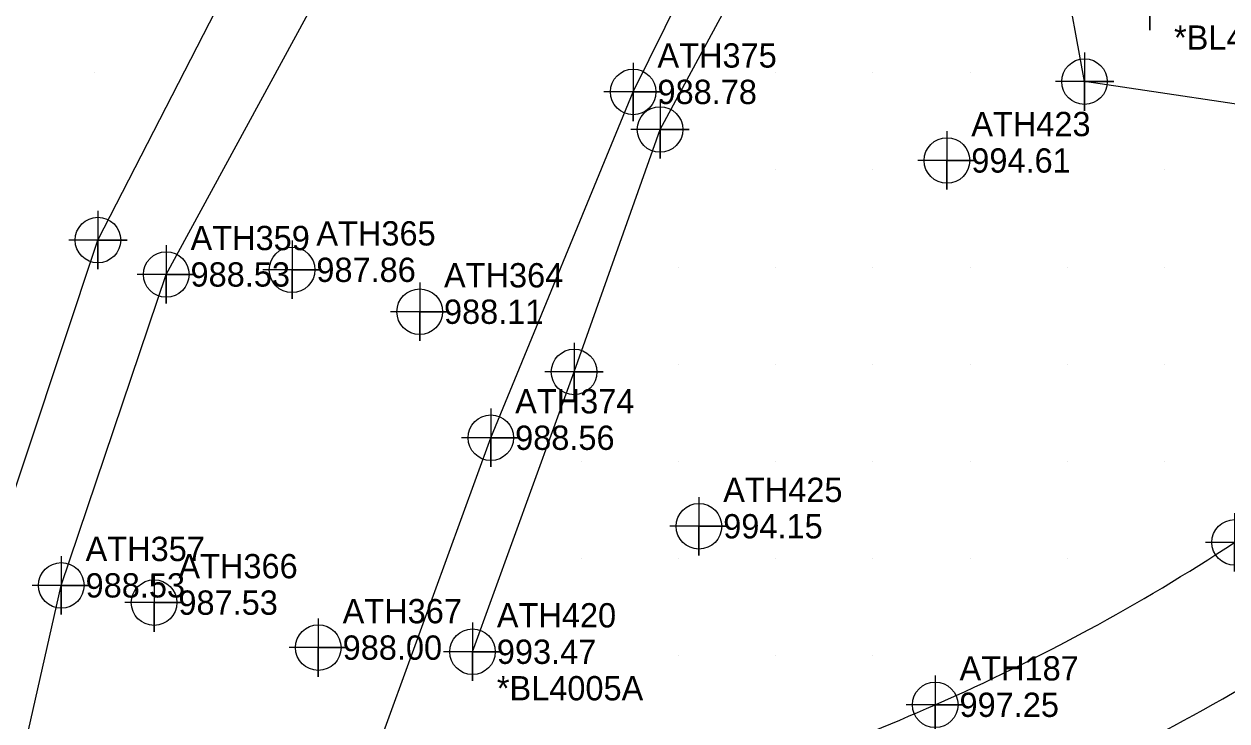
# Model space of a CAD drawing. Extents: x 1116680 to 1117499, y 661040 to 661703.
# Drawn here: x 1117062.7 to 1117186.4, y 661403.3 to 661475 of the extents above; entities that cross this region are included whole.
import ezdxf

# ---------------------------------------------------------------- set-up
doc = ezdxf.new("R2010")
doc.units = 0
for name, color, linetype in [('Exist DTM Breakline', 7, 'Continuous'), ('Exist DTM Breakline Cogo Comment', 7, 'Continuous'), ('Exist DTM Breakline Cogo Elevation', 7, 'Continuous'), ('Exist DTM Breakline Cogo Number', 7, 'Continuous'), ('Exist DTM Breakline Cogo Point CELL', 7, 'Continuous'), ('Exist DTM Crownline', 7, 'Continuous'), ('Exist DTM Drainline Cogo Elevation', 7, 'Continuous'), ('Exist DTM Drainline Cogo Number', 7, 'Continuous'), ('Exist DTM Drainline Cogo Point CELL', 7, 'Continuous'), ('Exist DTM QL2 LIDAR Elevation Point', 7, 'Continuous'), ('Exist DTM Regular Point CELL', 7, 'Continuous'), ('Exist DTM Regular Point Cogo Elevation', 7, 'Continuous'), ('Exist DTM Regular Point Cogo Number', 7, 'Continuous'), ('Exist DTM Regular Point Underwater CELL', 7, 'Continuous'), ('Exist DTM Regular Point Underwater Cogo Elevation', 7, 'Continuous'), ('Exist DTM Regular Point Underwater Cogo Number', 7, 'Continuous'), ('Exist Hydro Stream or Body of Water', 7, 'Continuous'), ('Exist Roads EOP', 7, 'Continuous'), ('Exist Roads EOP Cogo Elevation', 7, 'Continuous'), ('Exist Roads EOP Cogo Number', 7, 'Continuous'), ('Exist Roads EOP Cogo Point CELL', 7, 'Continuous')]:
    doc.layers.add(name, color=color, linetype=linetype)

msp = doc.modelspace()

# ---------------------------------------------------------------- linework, layer by layer
at = {"layer": 'Exist DTM Breakline'}
for points in [[(1117128.128, 661464.169), (1117144.878, 661495.181), (1117168.704, 661527.446), (1117200.502, 661571.22), (1117217.144, 661612.812), (1117257.559, 661667.144), (1117273.855, 661694.87)], [(1117194.27, 661465.73), (1117171.77, 661469.09), (1117169.6, 661480.945), (1117189.888, 661502.41), (1117205.863, 661515.329), (1117217.572, 661523.34), (1117225.692, 661514.312), (1117221.27, 661493.665), (1117211.404, 661481.256)], [(1117038.555, 661379.021), (1117059.605, 661420.588), (1117070.329, 661452.789), (1117088.813, 661488.846)], [(1117108.846, 661410.435), (1117119.29, 661439.222), (1117128.128, 661464.169)]]:
    msp.add_lwpolyline(points, dxfattribs=at)
at = {"layer": 'Exist DTM Breakline Cogo Point CELL'}
for points in [[(1117178.472, 661480.376), (1117178.472, 661474.376), (1117178.472, 661477.376), (1117181.472, 661477.376), (1117175.472, 661477.376)], [(1117171.77, 661472.09), (1117171.77, 661466.09), (1117171.77, 661469.09), (1117174.77, 661469.09), (1117168.77, 661469.09)], [(1117128.128, 661467.169), (1117128.128, 661461.169), (1117128.128, 661464.169), (1117131.128, 661464.169), (1117125.128, 661464.169)], [(1117070.329, 661455.789), (1117070.329, 661449.789), (1117070.329, 661452.789), (1117073.329, 661452.789), (1117067.329, 661452.789)], [(1117119.29, 661442.222), (1117119.29, 661436.222), (1117119.29, 661439.222), (1117122.29, 661439.222), (1117116.29, 661439.222)], [(1117108.846, 661413.435), (1117108.846, 661407.435), (1117108.846, 661410.435), (1117111.846, 661410.435), (1117105.846, 661410.435)], [(1117108.846, 661413.435), (1117108.846, 661407.435), (1117108.846, 661410.435), (1117111.846, 661410.435), (1117105.846, 661410.435)]]:
    msp.add_lwpolyline(points, dxfattribs=at)
for centre in [(1117171.77, 661469.09), (1117128.128, 661464.169), (1117070.329, 661452.789), (1117119.29, 661439.222), (1117108.846, 661410.435), (1117108.846, 661410.435)]:
    msp.add_circle(centre, 2.344, dxfattribs=at)
at = {"layer": 'Exist DTM Crownline'}
msp.add_spline([(1117128.608, 661382.881), (1117161.083, 661393.544), (1117193.928, 661410.345), (1117229.679, 661438.384), (1117257.918, 661472.931), (1117285.234, 661525.056), (1117305.735, 661573.245), (1117329.129, 661633.315)], degree=3, dxfattribs=at)
at = {"layer": 'Exist DTM Drainline Cogo Point CELL'}
for points in [[(1117125.362, 661471.034), (1117125.362, 661465.034), (1117125.362, 661468.034), (1117128.362, 661468.034), (1117122.362, 661468.034)], [(1117077.352, 661452.252), (1117077.352, 661446.252), (1117077.352, 661449.252), (1117080.352, 661449.252), (1117074.352, 661449.252)], [(1117110.725, 661435.453), (1117110.725, 661429.453), (1117110.725, 661432.453), (1117113.725, 661432.453), (1117107.725, 661432.453)], [(1117066.561, 661420.266), (1117066.561, 661414.266), (1117066.561, 661417.266), (1117069.561, 661417.266), (1117063.561, 661417.266)]]:
    msp.add_lwpolyline(points, dxfattribs=at)
for centre in [(1117125.362, 661468.034), (1117077.352, 661449.252), (1117110.725, 661432.453), (1117066.561, 661417.266)]:
    msp.add_circle(centre, 2.344, dxfattribs=at)
at = {"layer": 'Exist DTM QL2 LIDAR Elevation Point'}
for p, q in [((1117070, 661470), (1117070, 661470)), ((1117140, 661470), (1117140, 661470)), ((1117150, 661470), (1117150, 661470)), ((1117160, 661470), (1117160, 661470)), ((1117140, 661460), (1117140, 661460)), ((1117150, 661460), (1117150, 661460)), ((1117160, 661460), (1117160, 661460)), ((1117170, 661460), (1117170, 661460)), ((1117180, 661460), (1117180, 661460)), ((1117130, 661450), (1117130, 661450)), ((1117140, 661450), (1117140, 661450)), ((1117150, 661450), (1117150, 661450)), ((1117160, 661450), (1117160, 661450)), ((1117170, 661450), (1117170, 661450)), ((1117180, 661450), (1117180, 661450)), ((1117130, 661440), (1117130, 661440)), ((1117140, 661440), (1117140, 661440)), ((1117150, 661440), (1117150, 661440)), ((1117160, 661440), (1117160, 661440)), ((1117170, 661440), (1117170, 661440)), ((1117180, 661440), (1117180, 661440)), ((1117120, 661430), (1117120, 661430)), ((1117130, 661430), (1117130, 661430)), ((1117140, 661430), (1117140, 661430)), ((1117150, 661430), (1117150, 661430)), ((1117160, 661430), (1117160, 661430)), ((1117170, 661430), (1117170, 661430)), ((1117180, 661430), (1117180, 661430)), ((1117120, 661420), (1117120, 661420)), ((1117130, 661420), (1117130, 661420)), ((1117140, 661420), (1117140, 661420)), ((1117150, 661420), (1117150, 661420)), ((1117160, 661420), (1117160, 661420)), ((1117170, 661420), (1117170, 661420)), ((1117120, 661410), (1117120, 661410)), ((1117130, 661410), (1117130, 661410)), ((1117140, 661410), (1117140, 661410)), ((1117150, 661410), (1117150, 661410))]:
    msp.add_line(p, q, dxfattribs=at)
at = {"layer": 'Exist DTM Regular Point CELL'}
for points in [[(1117157.629, 661463.98), (1117157.629, 661457.98), (1117157.629, 661460.98), (1117160.629, 661460.98), (1117154.629, 661460.98)], [(1117132.124, 661426.346), (1117132.124, 661420.346), (1117132.124, 661423.346), (1117135.124, 661423.346), (1117129.124, 661423.346)]]:
    msp.add_lwpolyline(points, dxfattribs=at)
for centre in [(1117157.629, 661460.98), (1117132.124, 661423.346)]:
    msp.add_circle(centre, 2.344, dxfattribs=at)
at = {"layer": 'Exist DTM Regular Point Underwater CELL'}
for points in [[(1117090.29, 661452.73), (1117090.29, 661446.73), (1117090.29, 661449.73), (1117093.29, 661449.73), (1117087.29, 661449.73)], [(1117103.411, 661448.418), (1117103.411, 661442.418), (1117103.411, 661445.418), (1117106.411, 661445.418), (1117100.411, 661445.418)], [(1117076.104, 661418.491), (1117076.104, 661412.491), (1117076.104, 661415.491), (1117079.104, 661415.491), (1117073.104, 661415.491)], [(1117092.991, 661413.862), (1117092.991, 661407.862), (1117092.991, 661410.862), (1117095.991, 661410.862), (1117089.991, 661410.862)]]:
    msp.add_lwpolyline(points, dxfattribs=at)
for centre in [(1117090.29, 661449.73), (1117103.411, 661445.418), (1117076.104, 661415.491), (1117092.991, 661410.862)]:
    msp.add_circle(centre, 2.344, dxfattribs=at)
at = {"layer": 'Exist Hydro Stream or Body of Water'}
for points in [[(1117125.362, 661468.034), (1117140.152, 661498.019), (1117164.523, 661530.702), (1117196.253, 661574.433), (1117208.146, 661610.151), (1117250.567, 661671.867), (1117271.101, 661697.995)], [(1116885.259, 661065.084), (1116909.522, 661128.826), (1116941.429, 661187.261), (1116973.299, 661231.015), (1117008.806, 661288.675), (1117028.625, 661329.39), (1117037.259, 661346.044), (1117054.084, 661350.959), (1117065.864, 661380.085), (1117058.435, 661381.413), (1117066.561, 661417.266), (1117077.352, 661449.252), (1117098.924, 661488.98)], [(1116999.252, 661212.663), (1117035.553, 661269.03), (1117067.842, 661309.057), (1117080.473, 661351.773), (1117079.751, 661359.687), (1117095.986, 661391.983), (1117110.725, 661432.453), (1117125.362, 661468.034)]]:
    msp.add_lwpolyline(points, dxfattribs=at)
at = {"layer": 'Exist Roads EOP'}
for points in [[(1117102.286, 661387.333), (1117126.621, 661394.057), (1117156.418, 661404.979), (1117187.204, 661421.689), (1117219.891, 661448.41), (1117247.012, 661480.823), (1117275.546, 661531.18), (1117296.661, 661577.27), (1117320.803, 661635.676)], [(1117131.334, 661372.856), (1117166.321, 661382.847), (1117200.815, 661399.841), (1117238.067, 661430.322), (1117267.048, 661465.689), (1117295.472, 661519.132), (1117314.821, 661568.418)]]:
    msp.add_spline(points, degree=3, dxfattribs=at)
at = {"layer": 'Exist Roads EOP Cogo Point CELL'}
for points in [[(1117187.204, 661424.689), (1117187.204, 661418.689), (1117187.204, 661421.689), (1117190.204, 661421.689), (1117184.204, 661421.689)], [(1117156.418, 661407.979), (1117156.418, 661401.979), (1117156.418, 661404.979), (1117159.418, 661404.979), (1117153.418, 661404.979)]]:
    msp.add_lwpolyline(points, dxfattribs=at)
for centre in [(1117187.204, 661421.689), (1117156.418, 661404.979)]:
    msp.add_circle(centre, 2.344, dxfattribs=at)

# ---------------------------------------------------------------- texts
at = {"layer": 'Exist DTM Breakline Cogo Comment'}
for s, p in [('*BL4005D', (1117180.972, 661472.376)), ('*BL4005A', (1117111.346, 661405.435)), ('*BL4005A', (1117111.346, 661405.435))]:
    msp.add_text(s, height=2.5, dxfattribs=at).set_placement(p)
at = {"layer": 'Exist DTM Breakline Cogo Elevation'}
msp.add_text('993.47', height=2.5, dxfattribs=at).set_placement((1117111.346, 661409.185))
at = {"layer": 'Exist DTM Breakline Cogo Number'}
msp.add_text('ATH420', height=2.5, dxfattribs=at).set_placement((1117111.346, 661412.935))
at = {"layer": 'Exist DTM Drainline Cogo Elevation'}
for s, p in [('988.78', (1117127.862, 661466.784)), ('988.53', (1117079.852, 661448.002)), ('988.56', (1117113.225, 661431.203)), ('988.53', (1117069.061, 661416.016))]:
    msp.add_text(s, height=2.5, dxfattribs=at).set_placement(p)
at = {"layer": 'Exist DTM Drainline Cogo Number'}
for s, p in [('ATH375', (1117127.862, 661470.534)), ('ATH359', (1117079.852, 661451.752)), ('ATH374', (1117113.225, 661434.953)), ('ATH357', (1117069.061, 661419.766))]:
    msp.add_text(s, height=2.5, dxfattribs=at).set_placement(p)
at = {"layer": 'Exist DTM Regular Point Cogo Elevation'}
for s, p in [('994.61', (1117160.129, 661459.73)), ('994.15', (1117134.624, 661422.096))]:
    msp.add_text(s, height=2.5, dxfattribs=at).set_placement(p)
at = {"layer": 'Exist DTM Regular Point Cogo Number'}
for s, p in [('ATH423', (1117160.129, 661463.48)), ('ATH425', (1117134.624, 661425.846))]:
    msp.add_text(s, height=2.5, dxfattribs=at).set_placement(p)
at = {"layer": 'Exist DTM Regular Point Underwater Cogo Elevation'}
for s, p in [('987.86', (1117092.79, 661448.48)), ('988.11', (1117105.911, 661444.168)), ('987.53', (1117078.604, 661414.241)), ('988.00', (1117095.491, 661409.612))]:
    msp.add_text(s, height=2.5, dxfattribs=at).set_placement(p)
at = {"layer": 'Exist DTM Regular Point Underwater Cogo Number'}
for s, p in [('ATH365', (1117092.79, 661452.23)), ('ATH364', (1117105.911, 661447.918)), ('ATH366', (1117078.604, 661417.991)), ('ATH367', (1117095.491, 661413.362))]:
    msp.add_text(s, height=2.5, dxfattribs=at).set_placement(p)
at = {"layer": 'Exist Roads EOP Cogo Elevation'}
msp.add_text('997.25', height=2.5, dxfattribs=at).set_placement((1117158.918, 661403.729))
at = {"layer": 'Exist Roads EOP Cogo Number'}
msp.add_text('ATH187', height=2.5, dxfattribs=at).set_placement((1117158.918, 661407.479))

doc.saveas('drawing.dxf')
